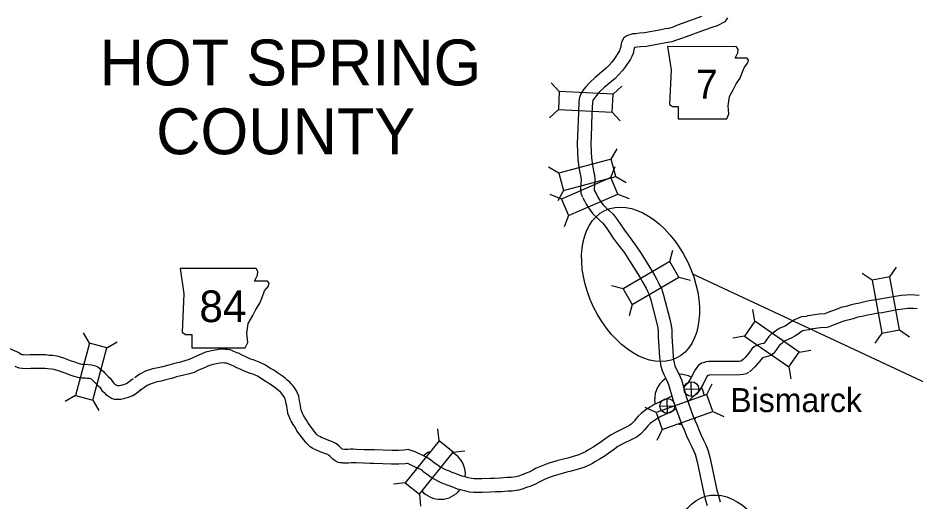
# Model space of a CAD drawing. Extents: x 1373862 to 1377080, y 1164775 to 1170415.
# Drawn here: x 1374006.5 to 1374204.1, y 1170176 to 1170282.4 of the extents above; entities that cross this region are included whole.
import ezdxf

# ---------------------------------------------------------------- set-up
doc = ezdxf.new("R2010")
doc.units = 0
for name, color, linetype in [('1', 7, 'Continuous'), ('Default', 7, 'Continuous'), ('R_Draft', 7, 'Continuous')]:
    doc.layers.add(name, color=color, linetype=linetype)

msp = doc.modelspace()

# ---------------------------------------------------------------- linework, layer by layer
at = {"layer": '1'}
msp.add_line((1374155.09, 1170226.04), (1374640.76, 1169998.76), dxfattribs=at)
at = {"layer": 'Default'}
for p, q in [((1374125.7, 1170266.15), (1374123.92, 1170268.1)), ((1374137.56, 1170265.59), (1374139.52, 1170267.37)), ((1374125.51, 1170262.19), (1374123.56, 1170260.41)), ((1374137.38, 1170261.64), (1374139.16, 1170259.69)), ((1374137.12, 1170251.27), (1374138.44, 1170253.56)), ((1374125.65, 1170248.19), (1374123.36, 1170249.51)), ((1374137.07, 1170247.23), (1374138.04, 1170249.68)), ((1374138.15, 1170247.45), (1374140.44, 1170246.13)), ((1374126.17, 1170242.5), (1374123.72, 1170243.47)), ((1374126.68, 1170244.36), (1374125.36, 1170242.08)), ((1374138.65, 1170243.59), (1374141.1, 1170242.62)), ((1374127.75, 1170238.87), (1374126.78, 1170236.41)), ((1374150.04, 1170228.72), (1374150.71, 1170231.27)), ((1374198.51, 1170225.35), (1374200.01, 1170227.53)), ((1374194.61, 1170224.64), (1374192.44, 1170226.13)), ((1374152.04, 1170225.3), (1374154.59, 1170224.63)), ((1374139.78, 1170222.72), (1374137.23, 1170223.39)), ((1374141.78, 1170219.31), (1374141.11, 1170216.75)), ((1374168.81, 1170215.58), (1374168.35, 1170218.18)), ((1374200.66, 1170213.67), (1374202.83, 1170212.17)), ((1374022.23, 1170210.73), (1374020.9, 1170213.02)), ((1374166.55, 1170212.34), (1374163.95, 1170211.87)), ((1374196.76, 1170212.95), (1374195.26, 1170210.78)), ((1374026.05, 1170209.71), (1374028.34, 1170211.03)), ((1374178.56, 1170208.78), (1374181.16, 1170209.25)), ((1374176.29, 1170205.54), (1374176.75, 1170202.94)), ((1374154.86, 1170199.02), (1374154.79, 1170202.28)), ((1374158.24, 1170199.44), (1374159.38, 1170201.83)), ((1374153.2, 1170200.61), (1374156.45, 1170200.69)), ((1374019.16, 1170199.26), (1374016.88, 1170197.93)), ((1374022.99, 1170198.23), (1374024.31, 1170195.95)), ((1374149.56, 1170195.32), (1374149.49, 1170198.57)), ((1374147.05, 1170195.47), (1374144.67, 1170196.6)), ((1374147.9, 1170196.91), (1374151.15, 1170196.98)), ((1374159.57, 1170195.71), (1374161.95, 1170194.58)), ((1374099.22, 1170189.26), (1374098.93, 1170191.88)), ((1374148.37, 1170191.74), (1374147.24, 1170189.35)), ((1374102.31, 1170186.78), (1374104.93, 1170187.07)), ((1374091.79, 1170179.98), (1374089.17, 1170179.69)), ((1374094.89, 1170177.51), (1374095.18, 1170174.88))]:
    msp.add_line(p, q, dxfattribs=at)
for points in [[(1374157.05, 1170282.71), (1374151.79, 1170280.78), (1374150.55, 1170280.31), (1374149.79, 1170280.07), (1374149.07, 1170279.95), (1374147.8, 1170279.71), (1374144.5, 1170279.11), (1374143.35, 1170279), (1374142.57, 1170278.92), (1374141.94, 1170278.86), (1374141.48, 1170278.76), (1374140.97, 1170278.58), (1374140.62, 1170278.42), (1374139.94, 1170277.98), (1374139.43, 1170277.02), (1374139.29, 1170276.29), (1374139.24, 1170276.03), (1374139.09, 1170275.41), (1374138.98, 1170275.12), (1374138.86, 1170274.9), (1374137.89, 1170273.45), (1374137.29, 1170272.67), (1374136.68, 1170271.96), (1374136.01, 1170271.31), (1374133.62, 1170269.28), (1374132.53, 1170268.27), (1374131.51, 1170267.16), (1374130.92, 1170266.37), (1374130.44, 1170265.65), (1374130.14, 1170264.84), (1374130.05, 1170264.09), (1374129.92, 1170261.49), (1374129.71, 1170256.34), (1374129.63, 1170254.84), (1374129.71, 1170252.68), (1374129.79, 1170251.31), (1374130.03, 1170249.47), (1374130.3, 1170247.99), (1374130.47, 1170247.34), (1374130.52, 1170246.66), (1374130.47, 1170245.91), (1374130.39, 1170244.78), (1374130.46, 1170243.77), (1374130.85, 1170242.88)], [(1374162.76, 1170282.42), (1374162.15, 1170281.56), (1374160.47, 1170280.68), (1374159.3, 1170280.29), (1374158.04, 1170279.87), (1374152.84, 1170277.96), (1374151.52, 1170277.47), (1374150.49, 1170277.15), (1374149.61, 1170277), (1374148.35, 1170276.76), (1374144.9, 1170276.13), (1374143.64, 1170276.02), (1374142.87, 1170275.94), (1374142.42, 1170275.89), (1374142.32, 1170275.87), (1374142.26, 1170275.85), (1374142.24, 1170275.73), (1374142.17, 1170275.39), (1374141.96, 1170274.55), (1374141.73, 1170273.89), (1374141.42, 1170273.33), (1374140.33, 1170271.7), (1374139.62, 1170270.78), (1374138.87, 1170269.9), (1374138.02, 1170269.08), (1374135.61, 1170267.04), (1374134.66, 1170266.15), (1374133.83, 1170265.25), (1374133.37, 1170264.63), (1374133.13, 1170264.27), (1374133.07, 1170264.13), (1374133.04, 1170263.83), (1374132.92, 1170261.36), (1374132.71, 1170256.19), (1374132.63, 1170254.82), (1374132.71, 1170252.83), (1374132.78, 1170251.59), (1374133, 1170249.93), (1374133.23, 1170248.64), (1374133.45, 1170247.83), (1374133.52, 1170246.65), (1374133.46, 1170245.72), (1374133.4, 1170244.78), (1374133.42, 1170244.49), (1374133.6, 1170244.07)], [(1374133.54, 1170244.2), (1374133.89, 1170243.56), (1374134.24, 1170242.9), (1374134.83, 1170241.97), (1374135.4, 1170241.23), (1374136.22, 1170240.39), (1374136.6, 1170240.08), (1374137.55, 1170239.18), (1374138.45, 1170237.99), (1374139.25, 1170236.82), (1374140.07, 1170235.62), (1374141.08, 1170234.24), (1374142.52, 1170232.35), (1374143.72, 1170230.5), (1374146.01, 1170226.85), (1374146.74, 1170225.58), (1374147.21, 1170224.77), (1374147.52, 1170224.23), (1374147.82, 1170223.55), (1374148.24, 1170222.8), (1374148.69, 1170221.32), (1374150.08, 1170216.06), (1374150.38, 1170214.62), (1374150.49, 1170213.68), (1374150.52, 1170212.38), (1374150.59, 1170211.14), (1374150.63, 1170210.18), (1374150.71, 1170208.98), (1374150.8, 1170207.91), (1374150.88, 1170207.13), (1374151.01, 1170206.41), (1374151.2, 1170205.79), (1374151.55, 1170204.99), (1374152.06, 1170203.99), (1374152.63, 1170202.69), (1374153.76, 1170198.8), (1374155.17, 1170194.84), (1374155.58, 1170193.79), (1374155.98, 1170192.86), (1374156.51, 1170191.51), (1374156.95, 1170190.54), (1374157.5, 1170189.39), (1374158.01, 1170188.37), (1374158.46, 1170187.31), (1374158.98, 1170185.33), (1374160.45, 1170178.37), (1374160.77, 1170177.24), (1374161.14, 1170175.85)], [(1374130.91, 1170242.75), (1374131.25, 1170242.14), (1374131.65, 1170241.39), (1374132.37, 1170240.24), (1374133.13, 1170239.25), (1374134.18, 1170238.19), (1374134.61, 1170237.83), (1374135.31, 1170237.18), (1374136.01, 1170236.24), (1374136.78, 1170235.13), (1374137.62, 1170233.88), (1374138.68, 1170232.44), (1374140.07, 1170230.63), (1374141.19, 1170228.88), (1374143.44, 1170225.3), (1374144.14, 1170224.09), (1374144.61, 1170223.27), (1374144.84, 1170222.87), (1374145.13, 1170222.21), (1374145.46, 1170221.61), (1374145.81, 1170220.5), (1374147.16, 1170215.38), (1374147.41, 1170214.14), (1374147.49, 1170213.46), (1374147.52, 1170212.26), (1374147.59, 1170211), (1374147.63, 1170210.02), (1374147.71, 1170208.74), (1374147.82, 1170207.62), (1374147.91, 1170206.73), (1374148.08, 1170205.71), (1374148.38, 1170204.73), (1374148.84, 1170203.7), (1374149.35, 1170202.71), (1374149.8, 1170201.67), (1374150.9, 1170197.88), (1374152.36, 1170193.79), (1374152.81, 1170192.64), (1374153.21, 1170191.71), (1374153.74, 1170190.35), (1374154.23, 1170189.27), (1374154.81, 1170188.07), (1374155.28, 1170187.12), (1374155.62, 1170186.33), (1374156.06, 1170184.63), (1374157.53, 1170177.65), (1374157.88, 1170176.44), (1374158.26, 1170175.03)], [(1374204.96, 1170221.27), (1374204.01, 1170221.36), (1374202.99, 1170221.43), (1374202.21, 1170221.36), (1374201.05, 1170221.23), (1374199.72, 1170221.06), (1374196.34, 1170220.44), (1374195.37, 1170220.31), (1374193.98, 1170220.05), (1374192.99, 1170219.86), (1374191.82, 1170219.59), (1374190.71, 1170219.37), (1374189.82, 1170219.1), (1374188.88, 1170218.84), (1374187.74, 1170218.59), (1374186.93, 1170218.28), (1374185.89, 1170217.91), (1374185.22, 1170217.64), (1374184.75, 1170217.41), (1374184.36, 1170217.27), (1374184.2, 1170217.23), (1374182.93, 1170217.15), (1374181.09, 1170216.86), (1374180.48, 1170216.75), (1374180.1, 1170216.63), (1374179.08, 1170216.53), (1374178.16, 1170216.22), (1374177.55, 1170215.88), (1374176.75, 1170215.37), (1374175.96, 1170214.84), (1374175.46, 1170214.53), (1374174.27, 1170214.07), (1374173.64, 1170213.66), (1374173.02, 1170213.22), (1374172.75, 1170212.98), (1374172.37, 1170212.71), (1374171.89, 1170212.23), (1374170.88, 1170210.78), (1374170.87, 1170210.77), (1374170.73, 1170210.72), (1374170.24, 1170210.59), (1374169.75, 1170210.44), (1374169.26, 1170210.27), (1374168.71, 1170210.02), (1374168.16, 1170209.55), (1374167.47, 1170208.55), (1374166.65, 1170207.61), (1374166.21, 1170207.2), (1374165.91, 1170206.93), (1374165.78, 1170206.83)], [(1374204.57, 1170218.29), (1374203.77, 1170218.37), (1374203.01, 1170218.42), (1374202.51, 1170218.38), (1374201.41, 1170218.25), (1374200.18, 1170218.09), (1374196.81, 1170217.47), (1374195.84, 1170217.35), (1374194.53, 1170217.1), (1374193.61, 1170216.93), (1374192.45, 1170216.66), (1374191.44, 1170216.46), (1374190.65, 1170216.22), (1374189.6, 1170215.93), (1374188.61, 1170215.71), (1374187.96, 1170215.46), (1374186.97, 1170215.11), (1374186.45, 1170214.9), (1374185.91, 1170214.64), (1374185.2, 1170214.39), (1374184.64, 1170214.25), (1374183.26, 1170214.17), (1374181.6, 1170213.91), (1374181.19, 1170213.83), (1374180.69, 1170213.68), (1374179.72, 1170213.58), (1374179.39, 1170213.47), (1374179.08, 1170213.3), (1374178.38, 1170212.85), (1374177.58, 1170212.32), (1374176.81, 1170211.84), (1374175.65, 1170211.38), (1374175.31, 1170211.17), (1374174.88, 1170210.87), (1374174.64, 1170210.65), (1374174.32, 1170210.41), (1374174.19, 1170210.29), (1374173.19, 1170208.86), (1374172.8, 1170208.45), (1374172.27, 1170208.07), (1374171.61, 1170207.85), (1374171.07, 1170207.7), (1374170.67, 1170207.58), (1374170.38, 1170207.48), (1374169.84, 1170206.7), (1374168.82, 1170205.54), (1374168.24, 1170204.99), (1374167.83, 1170204.62), (1374167.63, 1170204.46)], [(1374003.59, 1170210), (1374006.69, 1170208.68), (1374007.19, 1170208.35), (1374007.35, 1170208.28), (1374007.67, 1170208.25), (1374008.39, 1170208.18), (1374009.11, 1170208.27), (1374010.37, 1170208.25), (1374010.99, 1170208.25), (1374011.61, 1170208.26), (1374012.58, 1170208.25), (1374013.37, 1170208.15), (1374014.06, 1170208.09), (1374015.01, 1170207.98), (1374016.49, 1170207.52), (1374018, 1170206.97), (1374018.93, 1170206.64), (1374019.73, 1170206.36), (1374020.43, 1170206.15), (1374020.76, 1170206.12), (1374021, 1170206.11), (1374021.31, 1170206.11), (1374021.91, 1170206.08), (1374022.65, 1170206.02), (1374023.34, 1170205.84), (1374024.06, 1170205.52), (1374024.54, 1170205.19), (1374024.88, 1170204.89), (1374025.31, 1170204.51), (1374025.58, 1170204.14), (1374025.72, 1170203.99), (1374025.92, 1170203.83), (1374026.37, 1170203.44), (1374026.8, 1170203.03), (1374027.28, 1170202.31), (1374027.61, 1170201.99), (1374027.83, 1170201.76), (1374027.98, 1170201.65), (1374028.2, 1170201.48), (1374028.33, 1170201.42), (1374028.37, 1170201.42), (1374028.55, 1170201.43), (1374028.84, 1170201.44), (1374029.19, 1170201.5), (1374029.46, 1170201.56), (1374029.81, 1170201.69), (1374030.15, 1170201.81), (1374030.38, 1170201.9), (1374030.68, 1170202.09), (1374031.84, 1170202.95)], [(1374099.45, 1170183.48), (1374098.93, 1170183.87), (1374098.64, 1170184.07), (1374098.38, 1170184.26), (1374098.24, 1170184.35), (1374097.82, 1170184.69), (1374097.45, 1170185.01), (1374096.7, 1170185.53), (1374096.09, 1170185.82), (1374095.33, 1170186.17), (1374094.68, 1170186.5), (1374093.95, 1170186.82), (1374093.3, 1170187.08), (1374092.44, 1170187.33), (1374091.47, 1170187.18), (1374090.28, 1170187.1), (1374089.45, 1170187.12), (1374088.82, 1170187.13), (1374084.92, 1170187.3), (1374083.96, 1170187.27), (1374082.72, 1170187.31), (1374081.08, 1170187.38), (1374080.3, 1170187.4), (1374079.76, 1170187.4), (1374079.2, 1170187.37), (1374078.68, 1170187.36), (1374078.39, 1170187.37), (1374077.92, 1170187.4), (1374077.8, 1170187.5), (1374077.6, 1170187.69), (1374077.22, 1170188.09), (1374076.63, 1170188.59), (1374075.93, 1170188.98), (1374075.38, 1170189.16), (1374075.15, 1170189.23), (1374074.18, 1170189.6), (1374073.37, 1170189.97), (1374072.95, 1170190.18), (1374072.63, 1170190.39), (1374072.45, 1170190.53), (1374072.26, 1170190.74), (1374070.43, 1170193.14), (1374070.04, 1170193.84), (1374069.58, 1170194.49), (1374069.3, 1170194.97), (1374069.17, 1170195.26), (1374068.98, 1170195.68), (1374068.87, 1170196.03), (1374068.8, 1170196.48), (1374068.65, 1170197.5), (1374068.5, 1170198.05), (1374068.42, 1170198.47), (1374068.31, 1170199.06), (1374068.07, 1170199.73), (1374067.81, 1170200.3), (1374067.55, 1170200.68), (1374067.3, 1170201.04), (1374066.98, 1170201.49), (1374066.68, 1170201.82), (1374066.36, 1170202.18), (1374065.76, 1170202.65), (1374065.38, 1170202.97), (1374064.98, 1170203.32), (1374064.3, 1170203.8), (1374063.65, 1170204.25), (1374062.83, 1170204.79), (1374062.11, 1170205.17), (1374060.84, 1170206.02), (1374059.63, 1170206.6), (1374058.48, 1170207.04), (1374057.57, 1170207.3), (1374056.84, 1170207.65), (1374055.88, 1170208.12), (1374055.06, 1170208.54), (1374054.72, 1170208.66), (1374053.74, 1170209.05), (1374053.19, 1170209.26), (1374052.64, 1170209.35), (1374052.11, 1170209.38), (1374051.16, 1170209.41), (1374049.08, 1170209.07), (1374048.51, 1170208.9), (1374047.77, 1170208.76), (1374046.96, 1170208.4), (1374045.95, 1170207.95), (1374044.99, 1170207.52), (1374044.2, 1170207.14), (1374043.46, 1170206.92), (1374042.3, 1170206.6), (1374040.64, 1170206.24), (1374039.74, 1170205.94), (1374038.3, 1170205.57), (1374037.32, 1170205.3), (1374036.12, 1170205.09), (1374035.52, 1170204.89), (1374035.25, 1170204.79), (1374034.57, 1170204.57), (1374034.14, 1170204.37)], [(1374005.76, 1170205.7), (1374006.63, 1170205.33), (1374007.38, 1170205.27), (1374008.43, 1170205.15), (1374009.28, 1170205.27), (1374010.35, 1170205.25), (1374011.03, 1170205.25), (1374011.62, 1170205.26), (1374012.37, 1170205.25), (1374013.06, 1170205.16), (1374013.76, 1170205.11), (1374014.39, 1170205.03), (1374015.53, 1170204.68), (1374016.98, 1170204.15), (1374017.93, 1170203.81), (1374018.8, 1170203.5), (1374019.86, 1170203.19), (1374020.59, 1170203.12), (1374020.97, 1170203.11), (1374021.25, 1170203.11), (1374021.71, 1170203.09), (1374022.14, 1170203.06), (1374022.34, 1170203), (1374022.59, 1170202.89), (1374022.7, 1170202.82), (1374022.89, 1170202.65), (1374023.07, 1170202.49), (1374023.26, 1170202.22), (1374023.68, 1170201.78), (1374024, 1170201.52), (1374024.35, 1170201.22), (1374024.49, 1170201.09), (1374024.97, 1170200.37), (1374025.48, 1170199.88), (1374025.85, 1170199.49), (1374026.2, 1170199.24), (1374026.6, 1170198.94), (1374027.1, 1170198.68), (1374027.69, 1170198.43), (1374028.41, 1170198.42), (1374028.71, 1170198.43), (1374029.15, 1170198.46), (1374029.77, 1170198.55), (1374030.34, 1170198.69), (1374030.83, 1170198.87), (1374031.18, 1170198.99), (1374031.75, 1170199.21), (1374032.39, 1170199.62), (1374033.63, 1170200.54)], [(1374097.68, 1170181.06), (1374097.18, 1170181.43), (1374096.9, 1170181.62), (1374096.64, 1170181.81), (1374096.44, 1170181.95), (1374095.9, 1170182.38), (1374095.6, 1170182.64), (1374095.19, 1170182.93), (1374094.82, 1170183.11), (1374094.03, 1170183.47), (1374093.4, 1170183.78), (1374092.79, 1170184.05), (1374092.32, 1170184.24), (1374092.24, 1170184.26), (1374091.8, 1170184.2), (1374090.35, 1170184.1), (1374089.38, 1170184.12), (1374088.72, 1170184.14), (1374084.9, 1170184.3), (1374083.96, 1170184.27), (1374082.61, 1170184.31), (1374080.99, 1170184.38), (1374080.26, 1170184.4), (1374079.84, 1170184.4), (1374079.31, 1170184.37), (1374078.67, 1170184.36), (1374078.08, 1170184.37), (1374077.98, 1170184.39), (1374077.42, 1170184.43), (1374077, 1170184.52), (1374076.31, 1170184.85), (1374075.81, 1170185.25), (1374075.48, 1170185.57), (1374075.16, 1170185.9), (1374074.9, 1170186.12), (1374074.72, 1170186.22), (1374074.5, 1170186.3), (1374074.19, 1170186.38), (1374073.03, 1170186.83), (1374072.1, 1170187.25), (1374071.44, 1170187.57), (1374070.85, 1170187.97), (1374070.39, 1170188.34), (1374069.95, 1170188.83), (1374067.93, 1170191.48), (1374067.5, 1170192.23), (1374067.06, 1170192.86), (1374066.64, 1170193.57), (1374066.42, 1170194.04), (1374066.18, 1170194.61), (1374065.95, 1170195.31), (1374065.83, 1170196.03), (1374065.7, 1170196.91), (1374065.58, 1170197.38), (1374065.47, 1170197.89), (1374065.4, 1170198.28), (1374065.29, 1170198.61), (1374065.2, 1170198.8), (1374065.08, 1170198.96), (1374064.84, 1170199.32), (1374064.62, 1170199.62), (1374064.43, 1170199.84), (1374064.31, 1170199.98), (1374063.87, 1170200.32), (1374063.43, 1170200.69), (1374063.12, 1170200.96), (1374062.57, 1170201.35), (1374061.98, 1170201.76), (1374061.31, 1170202.2), (1374060.57, 1170202.59), (1374059.35, 1170203.41), (1374058.45, 1170203.84), (1374057.51, 1170204.19), (1374056.5, 1170204.49), (1374055.53, 1170204.95), (1374054.54, 1170205.44), (1374053.88, 1170205.77), (1374053.66, 1170205.85), (1374052.66, 1170206.25), (1374052.41, 1170206.35), (1374052.3, 1170206.37), (1374051.97, 1170206.38), (1374051.36, 1170206.4), (1374049.74, 1170206.13), (1374049.21, 1170205.98), (1374048.68, 1170205.88), (1374048.18, 1170205.66), (1374047.18, 1170205.21), (1374046.26, 1170204.8), (1374045.29, 1170204.33), (1374044.28, 1170204.03), (1374043.02, 1170203.69), (1374041.43, 1170203.34), (1374040.59, 1170203.06), (1374039.07, 1170202.67), (1374037.98, 1170202.38), (1374036.87, 1170202.17), (1374036.48, 1170202.04), (1374036.21, 1170201.95), (1374035.66, 1170201.77), (1374035.36, 1170201.63)], [(1374165.98, 1170206.96), (1374165.73, 1170206.82), (1374165.67, 1170206.81), (1374165.31, 1170206.76), (1374158.56, 1170206.74), (1374158.01, 1170206.62), (1374157.68, 1170206.52), (1374157.13, 1170206.37), (1374156.35, 1170205.9), (1374155.99, 1170205.43), (1374155.64, 1170204.88), (1374154.79, 1170203.22), (1374154.04, 1170201.98), (1374153.97, 1170201.9), (1374153.78, 1170201.73), (1374153.12, 1170201.11)], [(1374034.06, 1170204.34), (1374033.29, 1170203.94), (1374032.61, 1170203.4), (1374032.28, 1170203.18), (1374032.15, 1170203.13)], [(1374167.43, 1170204.33), (1374166.86, 1170204.02), (1374166.25, 1170203.85), (1374165.49, 1170203.76), (1374158.91, 1170203.74), (1374158.74, 1170203.7), (1374158.46, 1170203.63), (1374158.38, 1170203.61), (1374158.24, 1170203.39), (1374157.41, 1170201.76), (1374156.51, 1170200.27), (1374156.18, 1170199.85), (1374155.81, 1170199.52), (1374154.94, 1170198.71), (1374154.1, 1170197.93)], [(1374035.43, 1170201.67), (1374034.93, 1170201.41), (1374034.38, 1170200.98), (1374033.72, 1170200.53), (1374033.31, 1170200.36)], [(1374150.5, 1170199.11), (1374149.04, 1170198.38), (1374148.22, 1170198.01), (1374147.77, 1170197.78), (1374146.65, 1170197.28), (1374145.73, 1170196.7), (1374144.77, 1170196.07), (1374144.17, 1170195.65), (1374143.73, 1170195.28), (1374143.11, 1170194.69), (1374142.61, 1170194.09), (1374142.25, 1170193.67), (1374141.74, 1170193.12), (1374141.57, 1170192.94), (1374141.24, 1170192.67), (1374140.72, 1170192.42), (1374138.21, 1170191.19), (1374136.98, 1170190.54), (1374135.77, 1170189.62), (1374134.93, 1170189.01), (1374133.96, 1170188.34), (1374133.15, 1170187.85), (1374132.01, 1170187.17), (1374131.51, 1170186.87), (1374130.97, 1170186.58), (1374130.04, 1170186.19), (1374128.81, 1170185.79), (1374127.58, 1170185.46), (1374126.65, 1170185.22), (1374125.39, 1170184.89), (1374124.24, 1170184.59), (1374123.43, 1170184.32), (1374122.68, 1170184.06), (1374121.59, 1170183.64), (1374120.5, 1170183.15), (1374119.87, 1170182.78), (1374119.2, 1170182.44), (1374118.4, 1170182.1), (1374117.51, 1170181.79), (1374116.7, 1170181.51), (1374116.12, 1170181.36), (1374115.12, 1170181.2), (1374114.25, 1170181.19), (1374112.69, 1170181.05), (1374111.47, 1170180.99), (1374110.48, 1170180.93), (1374108.67, 1170180.89), (1374108.04, 1170180.89), (1374107, 1170180.9), (1374106.45, 1170180.94), (1374105.68, 1170181.14), (1374105, 1170181.31), (1374104.22, 1170181.5), (1374102.98, 1170181.98), (1374102.13, 1170182.31), (1374101.36, 1170182.63), (1374100.88, 1170182.79), (1374099.23, 1170183.61)], [(1374151.39, 1170196.2), (1374150.32, 1170195.67), (1374149.53, 1170195.31), (1374149.06, 1170195.07), (1374148.06, 1170194.63), (1374147.35, 1170194.18), (1374146.45, 1170193.59), (1374146.01, 1170193.28), (1374145.74, 1170193.04), (1374145.29, 1170192.62), (1374144.91, 1170192.17), (1374144.51, 1170191.69), (1374143.91, 1170191.04), (1374143.61, 1170190.73), (1374142.87, 1170190.12), (1374142.02, 1170189.72), (1374139.57, 1170188.52), (1374138.61, 1170188.01), (1374137.56, 1170187.21), (1374136.66, 1170186.56), (1374135.59, 1170185.83), (1374134.7, 1170185.28), (1374133.54, 1170184.6), (1374133, 1170184.27), (1374132.27, 1170183.87), (1374131.09, 1170183.38), (1374129.67, 1170182.91), (1374128.34, 1170182.56), (1374127.41, 1170182.32), (1374126.15, 1170181.99), (1374125.09, 1170181.71), (1374124.39, 1170181.48), (1374123.72, 1170181.25), (1374122.74, 1170180.87), (1374121.88, 1170180.48), (1374121.3, 1170180.14), (1374120.47, 1170179.72), (1374119.48, 1170179.3), (1374118.5, 1170178.96), (1374117.57, 1170178.63), (1374116.72, 1170178.42), (1374115.37, 1170178.2), (1374114.4, 1170178.19), (1374112.91, 1170178.05), (1374111.63, 1170177.99), (1374110.6, 1170177.93), (1374108.72, 1170177.89), (1374108.04, 1170177.89), (1374106.88, 1170177.9), (1374105.95, 1170177.96), (1374104.93, 1170178.24), (1374104.28, 1170178.4), (1374103.32, 1170178.63), (1374101.9, 1170179.19), (1374101.03, 1170179.52), (1374100.3, 1170179.82), (1374099.71, 1170180.02), (1374097.89, 1170180.93)]]:
    msp.add_lwpolyline(points, dxfattribs=at)
for points in [[(1374149.56, 1170276.06), (1374150.33, 1170270.99), (1374149.99, 1170263.29), (1374150.66, 1170262.87), (1374151.93, 1170262.87), (1374151.93, 1170260.16), (1374162.59, 1170260.16), (1374163.1, 1170261.26), (1374162.93, 1170263.04), (1374163.18, 1170265.07), (1374164.11, 1170266.67), (1374164.71, 1170267.86), (1374165.55, 1170269.13), (1374166.06, 1170270.48), (1374166.48, 1170271.58), (1374167.24, 1170272.51), (1374167.41, 1170273.1), (1374167.07, 1170273.52), (1374164.45, 1170273.52), (1374165.04, 1170274.71), (1374165.13, 1170275.47), (1374164.78, 1170276.05)], [(1374125.51, 1170262.19), (1374137.38, 1170261.64), (1374137.56, 1170265.59), (1374125.7, 1170266.15)], [(1374137.12, 1170251.27), (1374125.65, 1170248.19), (1374126.68, 1170244.36), (1374138.15, 1170247.45)], [(1374137.07, 1170247.23), (1374126.17, 1170242.5), (1374127.75, 1170238.87), (1374138.65, 1170243.59)], [(1374141.78, 1170219.31), (1374152.04, 1170225.3), (1374150.04, 1170228.72), (1374139.78, 1170222.72)], [(1374042.19, 1170227.21), (1374043.03, 1170221.62), (1374042.65, 1170213.16), (1374043.4, 1170212.69), (1374044.79, 1170212.69), (1374044.79, 1170209.71), (1374056.52, 1170209.71), (1374057.08, 1170210.92), (1374056.89, 1170212.88), (1374057.17, 1170215.11), (1374058.19, 1170216.88), (1374058.84, 1170218.18), (1374059.77, 1170219.58), (1374060.33, 1170221.07), (1374060.8, 1170222.28), (1374061.64, 1170223.3), (1374061.82, 1170223.95), (1374061.45, 1170224.42), (1374058.57, 1170224.42), (1374059.22, 1170225.72), (1374059.31, 1170226.56), (1374058.92, 1170227.2)], [(1374200.66, 1170213.67), (1374198.51, 1170225.35), (1374194.61, 1170224.64), (1374196.76, 1170212.95)], [(1374166.55, 1170212.34), (1374176.29, 1170205.54), (1374178.56, 1170208.78), (1374168.81, 1170215.58)], [(1374022.99, 1170198.23), (1374026.05, 1170209.71), (1374022.23, 1170210.73), (1374019.16, 1170199.26)], [(1374158.24, 1170199.44), (1374147.05, 1170195.47), (1374148.37, 1170191.74), (1374159.57, 1170195.71)], [(1374094.89, 1170177.51), (1374102.31, 1170186.78), (1374099.22, 1170189.26), (1374091.79, 1170179.98)]]:
    msp.add_lwpolyline(points, close=True, dxfattribs=at)
for centre in [(1374154.82, 1170200.65), (1374149.52, 1170196.95)]:
    msp.add_circle(centre, 1.63, dxfattribs=at)
for centre, start, end in [((1374152.21, 1170198.41), 62.3657, 89.861), ((1374152.21, 1170198.41), 124.8192, 191.4755), ((1374152.21, 1170198.41), 8.6923, 29.1085), ((1374152.21, 1170198.41), 307.8507, 310.2855), ((1374152.21, 1170198.41), 268.1973, 274.3559), ((1374099.53, 1170181.89), 115.8778, 131.2256), ((1374099.53, 1170181.89), 354.8306, 61.0256), ((1374099.53, 1170181.89), 164.7698, 166.6077), ((1374099.53, 1170181.89), 221.4363, 321.5366)]:
    msp.add_arc(centre, 5.5, start, end, dxfattribs=at)
at = {"layer": 'R_Draft'}
for centre, major_axis in [((1374143.62, 1170223.71), (7.87, -16.25)), ((1374162.82, 1170159.66), (4.91, -17.38))]:
    msp.add_ellipse(centre, major_axis=major_axis, ratio=0.635834, dxfattribs=at)

# ---------------------------------------------------------------- texts
at = {"layer": 'Default'}
for s, height, p in [('HOT SPRING', 10.107, (1374024.45, 1170267.52)), ('7', 6.34, (1374155.87, 1170264.62)), ('COUNTY', 10.107, (1374036.92, 1170252.36)), ('84', 6.97, (1374046.43, 1170215.4)), ('Bismarck', 5.28, (1374163.37, 1170195.59))]:
    msp.add_text(s, height=height, dxfattribs=at).set_placement(p)

doc.saveas('drawing.dxf')
